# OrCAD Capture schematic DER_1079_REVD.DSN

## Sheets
1 PAGE2: size B
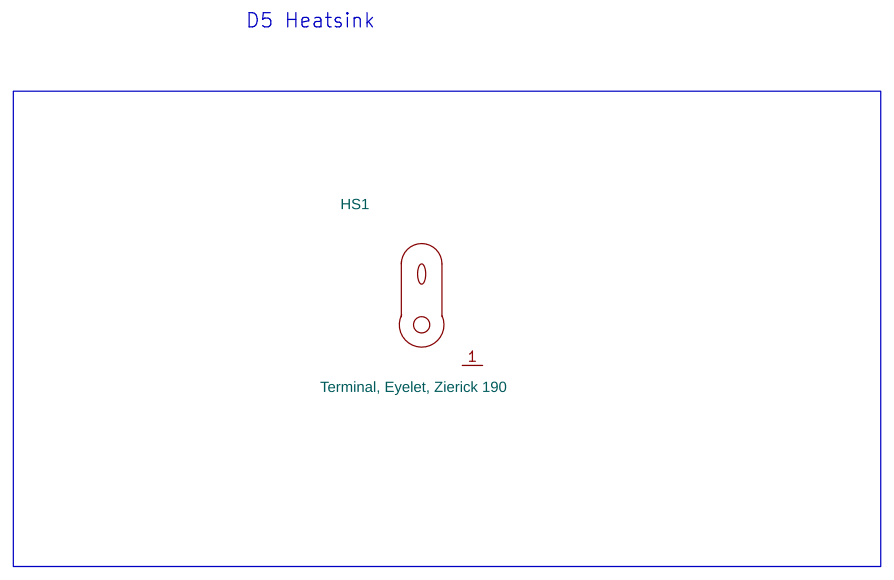
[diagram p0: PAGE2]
2 PAGE1: size D
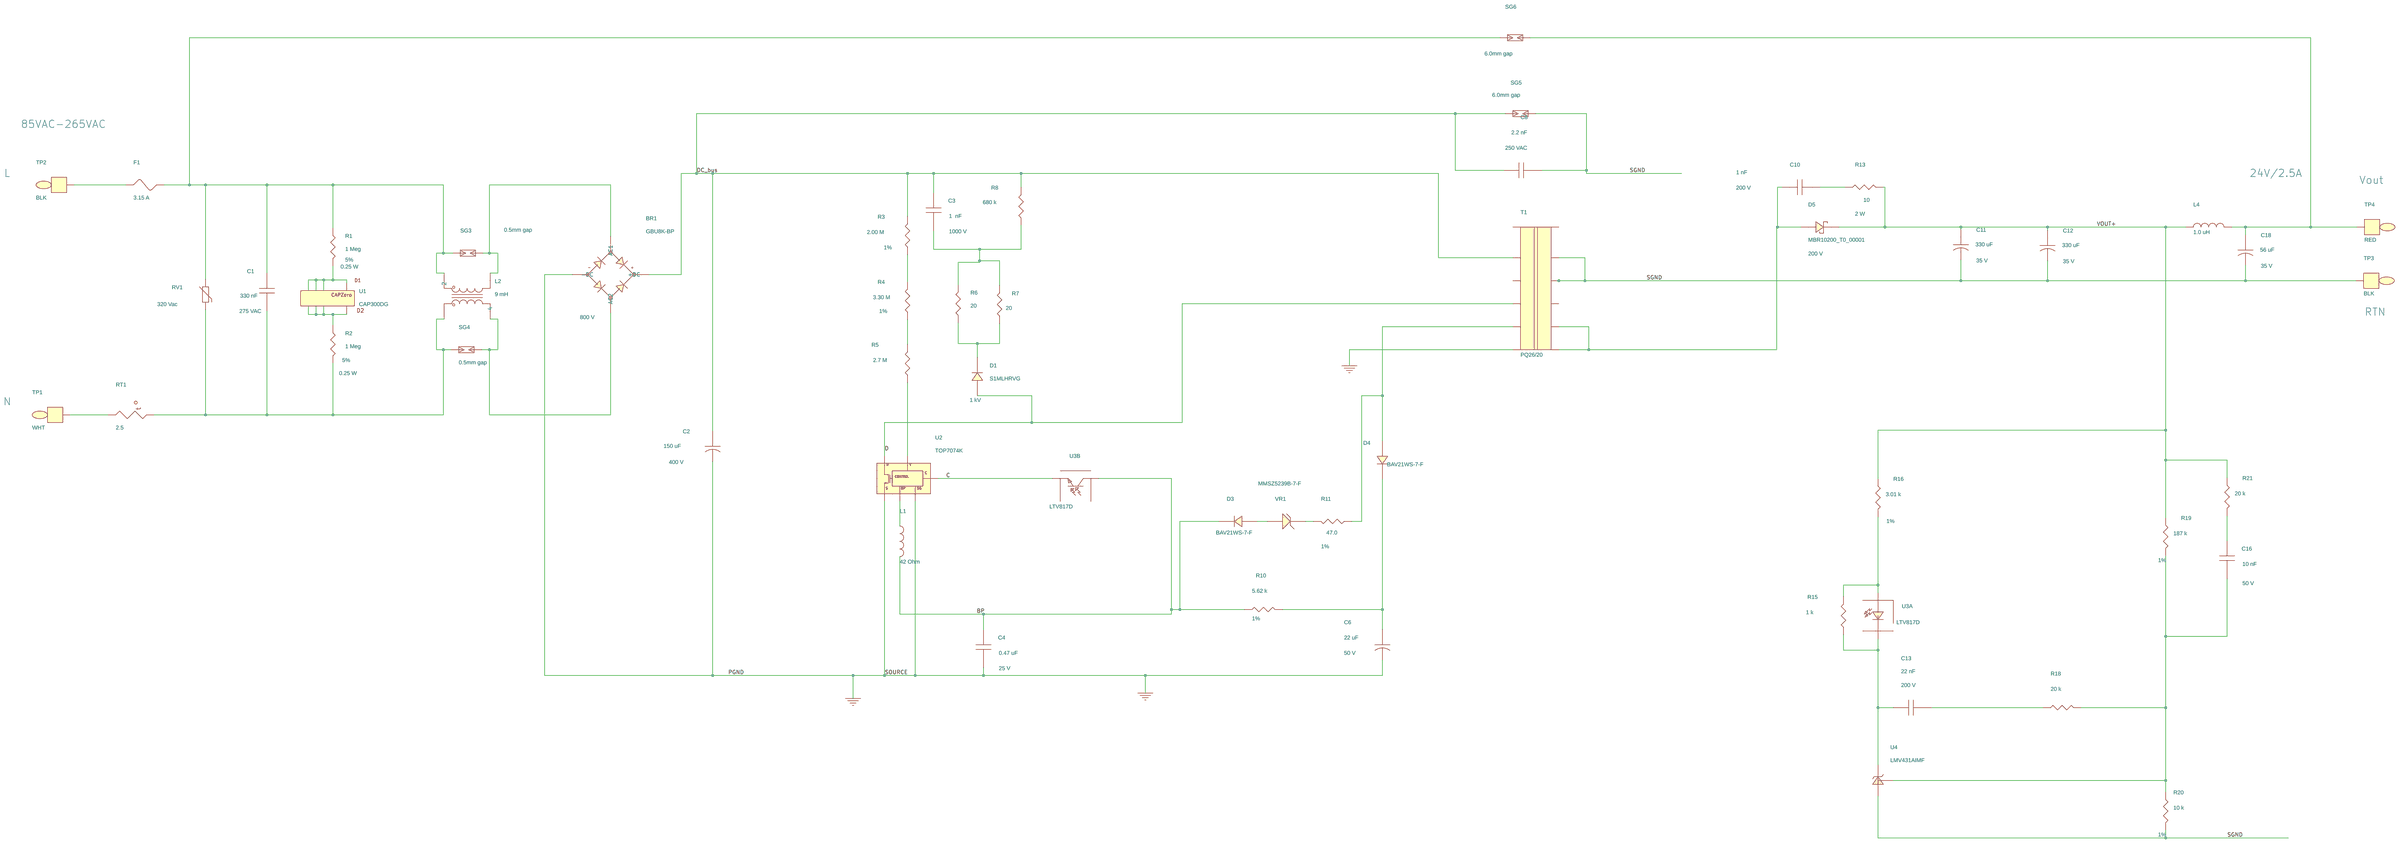
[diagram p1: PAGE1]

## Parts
sheet PAGE1
BR1  GBU8K-BP  [pidaxbridgegbu8]
C1  330 nF  [pinp_xcaprad15x8p5x14Hd040]
C2  150 uF  [picapcly18x33p5mmv]
C3  1  nF  [pismc1206]
C4  0.47 uF  [pismc0805]
C6  22 uF  [pipolcapclyd5mmd030]
C8  2.2 nF  [pinpycaprad540x290ls400040]
C10  1 nF  [pismc0805]
C11  330 uF  [pipolcapclyd10mm040]
C12  330 uF  [pipolcapclyd10mm040]
C13  22 nF  [pismc0805]
C16  10 nF  [pismc0805]
C18  56 uF  [pipolcapcyld250ls100030]
D1  S1MLHRVG  [pi_sm_sod-123_12]
D3  BAV21WS-7-F  [pismsod323]
D4  BAV21WS-7-F  [pismsod323]
D5  MBR10200_T0_00001  [pidvt0220acreva]
F1  3.15 A  [pi_rst_microfuse]
L1  42 Ohm  [INDC2012X105N]
L2  9 mH  [pi_toroid_balun_1]
L4  1.0 uH  [pi_choke_tokin_1]
R1  1 Meg  [pismr1206]
R2  1 Meg  [pismr1206]
R3  2.00 M  [pismr1206]
R4  3.30 M  [pismr1206]
R5  2.7 M  [pismr1206]
R6  20  [pismr1206]
R7  20  [pismr1206]
R8  680 k  [pismr1206]
R10  5.62 k  [pismr0805]
R11  47.0  [pismr0805]
R13  10  [pi2wvresd200ls300d040]
R15  1 k  [pismr0805]
R16  3.01 k  [pismr0603]
R18  20 k  [pismr0805]
R19  187 k  [pismr0603]
R20  10 k  [pismr0603]
R21  20 k  [pismr0805]
RT1  2.5  [pi_rad150x300ls200d030]
RV1  320 Vac  [pidisc500x225ls335x140040]
SG3  0.5mm gap  [PI_SPARK_GAP_0p5MM]
SG4  0.5mm gap  [PI_SPARK_GAP_0p5MM]
SG5  6.0mm gap  [PI_SPARK_GAP_6p0MM]
SG6  6.0mm gap  [PI_SPARK_GAP_6p0MM]
T1  PQ26/20  [pi_bobbin_bpq26_20_12p_2]
TP1  WHT  [pitpkeystone125x125]
TP2  BLK  [pitpkeystone125x125]
TP3  BLK  [pitpkeystone125x125]
TP4  RED  [pitpkeystone125x125]
U1  CAP300DG  [pi_ic_smd_so8_capzero]
U2  TOP7074K  [PI_eSOP-12B]
U3  LTV817D  [pi_dip4]  (sections A,B)
U4  LMV431AIMF  [pismsot23132]
VR1  MMSZ5239B-7-F  [pi_sm_sod-123_12]
sheet PAGE2
HS1  Terminal, Eyelet, Zierick 190  [pi_zierick190_eyelet]

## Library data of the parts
BR1 = DISCRETE_BRIDGE_+~~-: ALT_SYMBOLS: pidaxbridgegbu8_horz; Disp_Voltage: 800 V; FPLIST: pidaxbridgegbu8,pidaxbridgegbu8_horz; Part Number: 15-00347-00; ROOM: 1
C1 = CAP_NP: ALT_SYMBOLS: pinp_xcaprad15x8p5x14Hd040H; Disp_Voltage: 275 VAC; FPLIST: pinp_xcaprad15x8p5x14Hd040,pinp_xcaprad15x8p5x14Hd040H; Part Number: 20-09095-00; ROOM: 1; Voltage: 275 VAC
C2 = CAP_POL: ALT_SYMBOLS: picapcly18x33p5mmh; Disp_Voltage: 400 V; FPLIST: picapcly18x33p5mmv,picapcly18x33p5mmh; Part Number: 20-01385-00; ROOM: 1; Voltage: 400 V
C3 = CAP_NP: Disp_Voltage: 1000 V; Part Number: 20-01131-00; ROOM: 1; Voltage: 1000 V
C4 = CAP_NP: ALT_SYMBOLS: Unisem_RMCF0805UL; Disp_Voltage: 25 V; FPLIST: pismc0805,Unisem_RMCF0805UL; Part Number: 20-09182-00; ROOM: 1; Voltage: 25 V
C6 = CAP_POL: ALT_SYMBOLS: pipolcapclyd5x11mmd030H; Disp_Voltage: 50 V; FPLIST: pipolcapclyd5mmd030,pipolcapclyd5x11mmd030H; Part Number: 20-02059-00; ROOM: 1; Tol: 20; Voltage: 50 V
C8 = CAP_NP: ALT_SYMBOLS: pinpycaprad540x290ls400040h; Disp_Voltage: 250 VAC; FPLIST: pinpycaprad540x290ls400040,pinpycaprad540x290ls400040h; Part Number: 20-00376-00; ROOM: 2; Voltage: 250 VAC
C10 = CAP_NP: ALT_SYMBOLS: Unisem_RMCF0805UL,CC0805,pismc0805_1; Disp_Voltage: 200 V; FPLIST: pismc0805,Unisem_RMCF0805UL,CC0805,pismc0805_1; Part Number: 20-00737-00; ROOM: 2; Voltage: 200 V
C11 C12 = CAP_POL: ALT_SYMBOLS: pipolcapclyd395x630ls200030h; Disp_Voltage: 35 V; FPLIST: pipolcapclyd10mm040,pipolcapclyd395x630ls200030h; Note: Do Not Collect; Part Number: 20-00047-00; ROOM: 2; Voltage: 35 V
C13 = CAP_NP: ALT_SYMBOLS: Unisem_RMCF0805UL; Disp_Voltage: 200 V; FPLIST: pismc0805,Unisem_RMCF0805UL; Part Number: 20-00763-00; ROOM: 2; Voltage: 200 V
C16 = CAP_NP: Disp_Voltage: 50 V; Part Number: 20-09227-00; ROOM: 2; Voltage: 50 V
C18 = CAP_POL: ALT_SYMBOLS: pipolcapcyld250ls100030h; Disp_Voltage: 35 V; FPLIST: pipolcapcyld250ls100030,pipolcapcyld250ls100030h; Note: Do Not Collect; Part Number: 20-00042-00; ROOM: 2; Voltage: 35 V
D1 = DIODE: Disp_Voltage: 1 kV; Part Number: 15-01663-00; ROOM: 1
D3 D4 = DIODE: ALT_SYMBOLS: SOD323_UL_IPC,pismsod323_1; FPLIST: pismsod323,SOD323_UL_IPC,pismsod323_1; Part Number: 15-00385-00; ROOM: 1
D5 = DIODE_SCHOTTKY: Disp_Voltage: 200 V; Part Number: 15-02219-00
F1 = FUSE: ALT_SYMBOLS: pirstmicrofusehoz; FPLIST: pi_rst_microfuse,pirstmicrofusehoz; Part Number: 40-00071-00; ROOM: 1
L1 = INDUCTOR_BEAD: Part Number: 30-00656-00
L2 = INDUCTOR_4P_revG_1: Part Number: 30-00402-00
L4 = INDUCTOR: Part Number: 30-00498-00
R1 R2 = R: Disp_Power: 0.25 W; Disp_Tol: 5%; Part Number: 05-03554-00; ROOM: 1
R3 = R: Disp_Tol: 1%; Part Number: 05-03156-00; ROOM: 1
R4 = R: Disp_Tol: 1%; Part Number: 05-05359-00; ROOM: 1
R5 = R: Part Number: 05-01431-00; ROOM: 1
R6 R7 = R: Part Number: 05-01311-00; ROOM: 1
R8 = R: Part Number: 05-01420-00; ROOM: 1
R10 = R: ALT_SYMBOLS: Unisem_RMCF0805UL; Disp_Tol: 1%; FPLIST: pismr0805,Unisem_RMCF0805UL; Part Number: 05-03378-00; ROOM: 1
R11 = R: ALT_SYMBOLS: Unisem_RMCF0805UL; Disp_Tol: 1%; FPLIST: pismr0805,Unisem_RMCF0805UL; Part Number: 05-03476-00; ROOM: 1
R13 = R: ALT_SYMBOLS: pi2wresd200ls900d040,pi2wvresd200ls300d040,pi2wvresd200ls400d040; Disp_Power: 2 W; FPLIST: pi2wresd200ls725d040,pi2wresd200ls900d040,pi2wvresd200ls300d040,pi2wvresd200ls400d040; Part Number: 05-02956-00
R15 = R: ALT_SYMBOLS: Unisem_RMCF0805UL; FPLIST: pismr0805,Unisem_RMCF0805UL; Note: Changed; Part Number: 05-01519-00; ROOM: 2
R16 = R: ALT_SYMBOLS: Unisem_RMCF0603UL; Disp_Tol: 1%; FPLIST: pismr0603,Unisem_RMCF0603UL; Part Number: 05-01124-00; ROOM: 2
R18 = R: ALT_SYMBOLS: Unisem_RMCF0805UL; FPLIST: pismr0805,Unisem_RMCF0805UL; Part Number: 05-01550-00; ROOM: 2
R19 = R: ALT_SYMBOLS: Unisem_RMCF0603UL; Disp_Tol: 1%; FPLIST: pismr0603,Unisem_RMCF0603UL; Part Number: 05-01200-00; ROOM: 2
R20 = R: ALT_SYMBOLS: Unisem_RMCF0603UL; Disp_Tol: 1%; FPLIST: pismr0603,Unisem_RMCF0603UL; GROUP: 2; PCB Editor PCBFP: pismr0805; Part Number: 05-03182-00; ROOM: 2
R21 = R: Part Number: 05-01550-00; ROOM: 2
RT1 = THERMISTOR: ALT_SYMBOLS: pirad400x300ls200040_h; FPLIST: pi_rad150x300ls200d030,pirad400x300ls200040_h; Part Number: 90-00040-00; ROOM: 1
RV1 = VARISTOR: ALT_SYMBOLS: pi_rad450x550ls300d040_h; FPLIST: pidisc500x225ls335x140040,pi_rad450x550ls300d040_h; Part Number: 85-00018-00; ROOM: 1
SG3 SG4 = SPARK_GAP: Part Number: 66-00529-00; ROOM: 1
SG5 SG6 = SPARK_GAP: Part Number: 66-00525-00; ROOM: 1
T1 = BPQ26_20_12P_GENERIC: Part Number: 25-01140-00
TP1 = TESTPOINT: ALT_SYMBOLS: TP_5010-14; FPLIST: pitpkeystone125x125,TP_5010-14; Part Number: 35-00044-00; ROOM: 1
TP2 = TESTPOINT: ALT_SYMBOLS: TP_5010-14; FPLIST: pitpkeystone125x125,TP_5010-14; Part Number: 35-00042-00; ROOM: 1
TP3 = TESTPOINT: ALT_SYMBOLS: TP_5010-14; FPLIST: pitpkeystone125x125,TP_5010-14; Part Number: 35-00042-00; ROOM: 2
TP4 = TESTPOINT: ALT_SYMBOLS: TP_5010-14; FPLIST: pitpkeystone125x125,TP_5010-14; Part Number: 35-00043-00; ROOM: 2
U1 = CAPZero: Part Number: 10-01229-00; ROOM: 1
U2 = TOPSwitch-GaN_eSOP12B: Part Number: 10-01634-00
U3 = OPTO_A_B: Part Number: 53-00019-00
U4 = TL431_SOT-23_RCA: Part Number: 45-00019-00
VR1 = DIODE_ZENER: Part Number: 15-01087-00; ROOM: 1
HS1 = TERM_EYLT: Part Number: 60-00016-00

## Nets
GND: BR1.4(-DC) C2.2 C4.2 C6.2 T1.6 U2.4 U2.7
SGND: C8.2 C11.2 C12.2 C18.2 R20.2 SG5.2 T1.10 T1.11 TP3.1 U4.3(A)
BP: C4.1 D3.1 L1.2 R10.1 U3.4(C)
C: U2.3 U3.3(E)
D: D1.2 T1.4 U2.6
DC_bus: BR1.1(+DC) C2.1 C3.1 C8.1 R3.1 R8.1 SG5.1 T1.2
VOUT+: C11.1 C12.1 D5.1 L4.1 R13.1 R16.1 R19.1 R21.1
N9484136: R3.2 R4.1
N9484140: R4.2 R5.1
N12558827: C6.1 D4.1 R10.2
N12559431: D4.2 R11.1 T1.5
N12559644: C3.2 R6.1 R7.1 R8.2
N12560793: C10.1 D5.2 T1.7 T1.8
N12561948: C16.2 R18.2 R19.2 R20.1 U4.1(VREF)
N12562020: C13.1 R15.2 U3.2(C) U4.2(C)
N12562074: R15.1 R16.2 U3.1(A)
N12562376: C16.1 R21.2
N12562817: C13.2 R18.1
N12569802: F1.1 TP2.1
N12569814: RT1.1 TP1.1
N12570058: C1.1 F1.2 L2.4(2) R1.1 RV1.1 SG3.2 SG6.1
N12570065: C1.2 L2.1 R2.2 RT1.2 RV1.2 SG4.2
N12570840: BR1.2(AC1) L2.3 SG3.1
N12570848: BR1.3(AC2) L2.2(4) SG4.1
N12633188: C10.2 R13.2
N12979761: R1.2 U1.1(NC1) U1.2(D1) U1.3(NC2) U1.4(NC3)
N12979769: R2.1 U1.5(NC4) U1.6(NC5) U1.7(D2) U1.8(NC8)
N12981657: R5.2 U2.1
N12986702: D1.1 R6.2 R7.2
N12993570: D3.2 VR1.2
N12993578: R11.2 VR1.1
N13029630: C18.1 L4.2 SG6.2 TP4.1
N13057131: L1.1 U2.2

Not connected (* = marked no-connect by the designer): HS1 1; T1 1 3 9 12; U2 8 9 10 11 12 13

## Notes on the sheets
sheet 1
- D5 Heatsink
sheet 2
- 85VAC-265VAC
- L
- 24V/2.5A
- Vout
- RTN
- N
